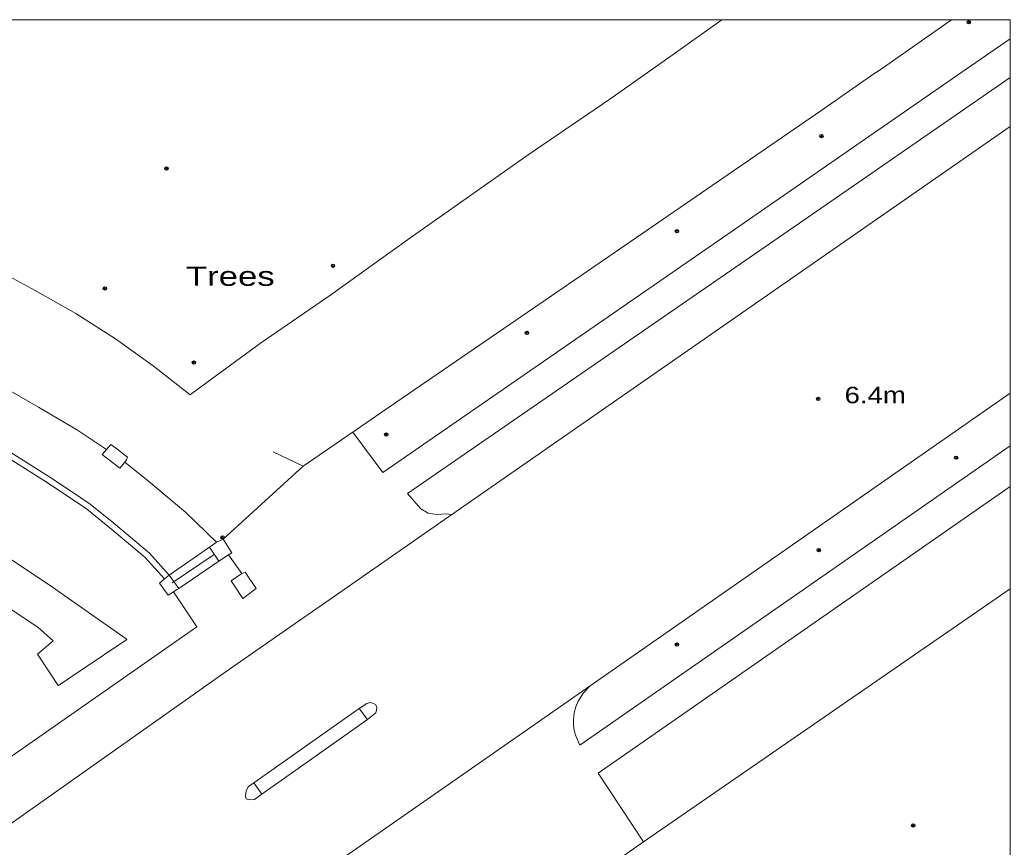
# Model space of a CAD drawing. Extents: x 528790 to 529292, y 179350 to 179856.
# Drawn here: x 529200.1 to 529290.2, y 179780.8 to 179856 of the extents above; entities that cross this region are included whole.
import ezdxf

# ---------------------------------------------------------------- set-up
doc = ezdxf.new("R2010")
doc.units = 0
doc.header["$LTSCALE"] = 0.6
doc.header["$PDMODE"] = 32
doc.header["$PDSIZE"] = 0.3
for name, color, linetype, lineweight in [('1', 7, 'Continuous', 13), ('2', 7, 'Continuous', 13), ('7', 7, 'Continuous', 13)]:
    doc.layers.add(name, color=color, linetype=linetype, lineweight=lineweight)
for name, color, linetype in [('3', 7, 'Continuous'), ('4', 7, 'Continuous'), ('5', 7, 'Continuous')]:
    doc.layers.add(name, color=color, linetype=linetype)

msp = doc.modelspace()

# ---------------------------------------------------------------- linework, layer by layer
at = {"layer": '1'}
for points in [[(529198.5, 179833.05), (529201.5, 179831.4), (529205.2, 179829.3), (529208.8, 179827), (529212.25, 179824.55), (529215.6, 179821.9), (529215.75, 179822.05), (529222, 179826.6), (529228.4, 179831), (529235.6, 179836.15), (529246.35, 179843.75), (529253.8, 179848.8), (529259.25, 179852.65), (529263.987, 179856.024), (529112.683, 179856.024)], [(529263.987, 179856.024), (529259.25, 179852.65), (529253.8, 179848.8), (529246.35, 179843.75), (529235.6, 179836.15), (529228.4, 179831), (529222, 179826.6), (529215.75, 179822.05), (529215.6, 179821.9), (529212.25, 179824.55), (529208.8, 179827), (529205.2, 179829.3), (529201.5, 179831.4), (529198.5, 179833.05)], [(529198.65, 179822.6), (529201.8, 179820.8), (529205.35, 179818.7), (529208, 179816.95), (529208.4, 179817.4), (529208.8, 179817.1), (529209.9, 179816.25), (529209.8, 179816), (529209.65, 179815.8), (529211.8, 179814.05), (529215.2, 179811.2), (529218, 179808.5), (529218.6, 179808.8), (529225.892, 179815.426), (529230.35, 179818.5), (529230.391, 179818.529), (529233.25, 179820.5), (529252.25, 179833.5), (529273, 179847.75), (529277.8, 179851.1), (529278.3, 179851.4), (529284.881, 179856.024), (529263.987, 179856.024)], [(529193.75, 179779.8), (529195, 179780.25), (529196.2, 179780.75), (529215.881, 179794.64), (529218.8, 179796.7), (529225.868, 179801.613), (529227.601, 179802.818), (529239.4, 179811.019), (529238.871, 179811.099), (529238.043, 179811.018), (529237.268, 179811.152), (529236.6, 179811.553), (529235.371, 179812.942), (529272.218, 179838.358), (529290.22, 179850.775), (529290.22, 179854.287)], [(529290.22, 179854.287), (529285.342, 179850.916), (529263.256, 179835.656), (529233.132, 179814.843), (529230.391, 179818.529), (529230.35, 179818.5), (529225.892, 179815.426), (529218.6, 179808.8), (529219.4, 179807.55), (529219.1, 179807.35), (529218.2, 179806.8), (529214.561, 179804.31), (529214.399, 179804.201), (529214.1, 179804), (529216.2, 179800.8), (529193.95, 179785.3)], [(529198.467, 179817.178), (529202.731, 179814.497), (529205.276, 179812.817), (529206.507, 179811.975), (529208.647, 179810.233), (529211.903, 179807.505), (529213.704, 179805.508), (529217.35, 179808.05), (529218, 179808.5), (529215.2, 179811.2), (529211.8, 179814.05), (529209.65, 179815.8), (529209.2, 179815.25), (529207.6, 179816.5), (529208, 179816.95), (529205.35, 179818.7), (529201.8, 179820.8), (529198.65, 179822.6)], [(529290.22, 179817.266), (529251.05, 179790.05), (529250.7, 179790.9), (529250.55, 179791.4), (529250.5, 179791.9), (529250.5, 179792.4), (529250.55, 179793), (529250.7, 179793.55), (529250.9, 179794.05), (529251.4, 179794.8), (529252, 179795.45), (529230.4, 179780.4)], [(529253.6, 179779), (529256.852, 179781.245), (529252.72, 179787.516), (529290.22, 179813.583), (529290.22, 179817.266)], [(529193.95, 179785.3), (529216.2, 179800.8), (529214.1, 179804), (529213.6, 179803.7), (529212.8, 179804.8), (529213.266, 179805.173), (529211.52, 179807.108), (529208.297, 179809.809), (529206.178, 179811.534), (529204.969, 179812.36), (529202.433, 179814.035), (529198.187, 179816.704)], [(529198.187, 179816.704), (529202.433, 179814.035), (529204.969, 179812.36), (529206.178, 179811.534), (529208.297, 179809.809), (529211.52, 179807.108), (529213.266, 179805.173), (529213.554, 179805.394), (529213.694, 179805.501), (529213.704, 179805.508), (529211.903, 179807.505), (529208.647, 179810.233), (529206.507, 179811.975), (529205.276, 179812.817), (529202.731, 179814.497), (529198.467, 179817.178)], [(529199.16, 179807.038), (529202.771, 179804.622), (529209.769, 179799.718), (529209.837, 179799.67), (529205.674, 179796.869), (529203.893, 179795.67), (529203.606, 179795.477), (529201.699, 179798.343), (529203.13, 179799.547), (529201.74, 179800.789), (529196.758, 179804.067)], [(529196.758, 179804.067), (529201.74, 179800.789), (529203.13, 179799.547), (529201.699, 179798.343), (529203.606, 179795.477), (529203.893, 179795.67), (529205.674, 179796.869), (529209.837, 179799.67), (529209.769, 179799.718), (529202.771, 179804.622), (529199.16, 179807.038)]]:
    msp.add_lwpolyline(points, dxfattribs=at)
for points in [[(529290.22, 179854.287), (529290.22, 179856.024), (529284.881, 179856.024), (529278.3, 179851.4), (529277.8, 179851.1), (529273, 179847.75), (529252.25, 179833.5), (529233.25, 179820.5), (529230.391, 179818.529), (529233.132, 179814.843), (529263.256, 179835.656), (529285.342, 179850.916)], [(529290.22, 179850.775), (529272.218, 179838.358), (529235.371, 179812.942), (529236.6, 179811.553), (529237.268, 179811.152), (529238.043, 179811.018), (529238.871, 179811.099), (529239.4, 179811.019), (529239.43, 179811.04), (529239.8, 179811.3), (529290.22, 179846.321)], [(529290.22, 179846.321), (529239.8, 179811.3), (529239.43, 179811.04), (529239.4, 179811.019), (529227.601, 179802.818), (529225.868, 179801.613), (529218.8, 179796.7), (529215.881, 179794.64), (529196.2, 179780.75), (529195, 179780.25), (529206.62, 179763.69), (529206.95, 179764.05), (529207.9, 179764.9), (529208.95, 179765.8), (529227.282, 179778.278), (529230.4, 179780.4), (529252, 179795.45), (529290.22, 179822.055)], [(529290.22, 179822.055), (529252, 179795.45), (529251.4, 179794.8), (529250.9, 179794.05), (529250.7, 179793.55), (529250.55, 179793), (529250.5, 179792.4), (529250.5, 179791.9), (529250.55, 179791.4), (529250.7, 179790.9), (529251.05, 179790.05), (529290.22, 179817.266)], [(529209.65, 179815.8), (529209.8, 179816), (529209.9, 179816.25), (529208.8, 179817.1), (529208.4, 179817.4), (529208, 179816.95), (529207.6, 179816.5), (529209.2, 179815.25)], [(529290.22, 179804.278), (529290.22, 179813.583), (529252.72, 179787.516), (529256.852, 179781.245)], [(529217.35, 179808.05), (529218.2, 179806.8), (529219.1, 179807.35), (529219.4, 179807.55), (529218.6, 179808.8), (529218, 179808.5)], [(529218.2, 179806.8), (529217.35, 179808.05), (529213.704, 179805.508), (529214.561, 179804.31)], [(529220.3, 179805.65), (529219.35, 179805), (529220.4, 179803.4), (529221.6, 179804.3), (529220.6, 179805.8)], [(529219.35, 179805), (529220.3, 179805.65), (529220.6, 179805.8), (529221.6, 179804.3), (529220.4, 179803.4)], [(529214.1, 179804), (529214.399, 179804.201), (529214.561, 179804.31), (529213.704, 179805.508), (529213.694, 179805.501), (529213.554, 179805.394), (529213.266, 179805.173), (529212.8, 179804.8), (529213.6, 179803.7)], [(529290.22, 179741.025), (529290.22, 179804.278), (529256.852, 179781.245), (529253.6, 179779), (529255.4, 179776.05), (529259.35, 179770.4), (529259.95, 179769.5), (529260.9, 179767.8), (529261.4, 179766.7), (529269.1, 179751.6), (529270.75, 179748.3), (529271.8, 179745.9), (529272.75, 179744), (529274.8, 179738.75), (529275, 179738.3), (529275.7, 179737.7), (529276.2, 179737.4), (529276.75, 179737.3), (529277.95, 179737.1), (529278.9, 179737.15), (529279.8, 179737.25), (529281, 179737.6), (529285.6, 179739.3)], [(529220.713, 179785.172), (529220.63, 179785.444), (529220.714, 179785.863), (529220.887, 179786.269), (529221.409, 179786.636), (529230.996, 179793.382), (529231.668, 179793.855), (529231.999, 179793.935), (529232.297, 179793.852), (529232.506, 179793.705), (529232.59, 179793.475), (529232.569, 179793.266), (529232.485, 179792.994), (529231.754, 179792.385), (529222.137, 179785.609), (529221.99, 179785.506), (529221.466, 179785.109), (529220.985, 179785.088)], [(529232.485, 179792.994), (529232.569, 179793.266), (529232.59, 179793.475), (529232.506, 179793.705), (529232.297, 179793.852), (529231.999, 179793.935), (529231.668, 179793.855), (529230.996, 179793.382), (529231.754, 179792.385)], [(529231.754, 179792.385), (529230.996, 179793.382), (529221.409, 179786.636), (529222.137, 179785.609)], [(529222.137, 179785.609), (529221.409, 179786.636), (529220.887, 179786.269), (529220.714, 179785.863), (529220.63, 179785.444), (529220.713, 179785.172), (529220.985, 179785.088), (529221.466, 179785.109), (529221.99, 179785.506)]]:
    msp.add_lwpolyline(points, close=True, dxfattribs=at)
at = {"layer": '2'}
for p, q in [((529277.8, 179851.1), (529273, 179847.75)), ((529252, 179795.45), (529290.22, 179822.055)), ((529225.892, 179815.426), (529223.147, 179816.729)), ((529225.892, 179815.426), (529218.6, 179808.8)), ((529227.601, 179802.818), (529239.4, 179811.019)), ((529217.35, 179808.05), (529218, 179808.5)), ((529218, 179808.5), (529218.6, 179808.8)), ((529217.35, 179808.05), (529213.704, 179805.508)), ((529213.97, 179804.81), (529217.79, 179807.4)), ((529218.2, 179806.8), (529217.35, 179808.05)), ((529219.1, 179807.35), (529218.2, 179806.8)), ((529219.1, 179807.35), (529220.3, 179805.65)), ((529218.2, 179806.8), (529214.561, 179804.31)), ((529213.704, 179805.508), (529214.561, 179804.31)), ((529256.852, 179781.245), (529290.22, 179804.278)), ((529227.601, 179802.818), (529225.868, 179801.613)), ((529221.409, 179786.636), (529230.996, 179793.382)), ((529230.996, 179793.382), (529231.754, 179792.385)), ((529231.754, 179792.385), (529222.137, 179785.609)), ((529221.409, 179786.636), (529222.137, 179785.609)), ((529253.6, 179779), (529256.852, 179781.245))]:
    msp.add_line(p, q, dxfattribs=at)
for points in [[(529198.5, 179833.05), (529201.5, 179831.4), (529205.2, 179829.3), (529208.8, 179827), (529212.25, 179824.55), (529215.6, 179821.9), (529215.75, 179822.05), (529222, 179826.6), (529228.4, 179831), (529235.6, 179836.15), (529246.35, 179843.75), (529253.8, 179848.8), (529259.25, 179852.65), (529263.987, 179856.024)], [(529284.881, 179856.024), (529278.3, 179851.4), (529277.8, 179851.1)], [(529230.391, 179818.529), (529233.132, 179814.843), (529263.256, 179835.656), (529285.342, 179850.916), (529290.22, 179854.287)], [(529290.22, 179850.775), (529272.218, 179838.358), (529235.371, 179812.942), (529236.6, 179811.553), (529237.268, 179811.152), (529238.043, 179811.018), (529238.871, 179811.099), (529239.4, 179811.019)], [(529230.391, 179818.529), (529233.25, 179820.5), (529252.25, 179833.5), (529273, 179847.75)], [(529239.4, 179811.019), (529239.43, 179811.04), (529239.8, 179811.3), (529290.22, 179846.321)], [(529198.65, 179822.6), (529201.8, 179820.8), (529205.35, 179818.7), (529208, 179816.95)], [(529225.892, 179815.426), (529230.35, 179818.5), (529230.391, 179818.529)], [(529208, 179816.95), (529208.4, 179817.4), (529208.8, 179817.1), (529209.9, 179816.25), (529209.8, 179816), (529209.65, 179815.8)], [(529252, 179795.45), (529251.4, 179794.8), (529250.9, 179794.05), (529250.7, 179793.55), (529250.55, 179793), (529250.5, 179792.4), (529250.5, 179791.9), (529250.55, 179791.4), (529250.7, 179790.9), (529251.05, 179790.05), (529290.22, 179817.266)], [(529213.266, 179805.173), (529211.52, 179807.108), (529208.297, 179809.809), (529206.178, 179811.534), (529204.969, 179812.36), (529202.433, 179814.035), (529198.187, 179816.704)], [(529213.704, 179805.508), (529211.903, 179807.505), (529208.647, 179810.233), (529206.507, 179811.975), (529205.276, 179812.817), (529202.731, 179814.497), (529198.467, 179817.178)], [(529209.65, 179815.8), (529209.2, 179815.25), (529207.6, 179816.5), (529208, 179816.95)], [(529218, 179808.5), (529215.2, 179811.2), (529211.8, 179814.05), (529209.65, 179815.8)], [(529256.852, 179781.245), (529252.72, 179787.516), (529290.22, 179813.583)], [(529218.6, 179808.8), (529219.4, 179807.55), (529219.1, 179807.35)], [(529196.758, 179804.067), (529201.74, 179800.789), (529203.13, 179799.547), (529201.699, 179798.343), (529203.606, 179795.477), (529203.893, 179795.67), (529205.674, 179796.869), (529209.837, 179799.67), (529209.769, 179799.718), (529202.771, 179804.622), (529199.16, 179807.038)], [(529214.1, 179804), (529213.6, 179803.7), (529212.8, 179804.8), (529213.266, 179805.173)], [(529213.266, 179805.173), (529213.554, 179805.394), (529213.694, 179805.501), (529213.704, 179805.508)], [(529214.1, 179804), (529216.2, 179800.8), (529193.95, 179785.3)], [(529214.561, 179804.31), (529214.399, 179804.201), (529214.1, 179804)], [(529225.868, 179801.613), (529218.8, 179796.7), (529215.881, 179794.64)], [(529227.282, 179778.278), (529230.4, 179780.4), (529252, 179795.45)], [(529215.881, 179794.64), (529196.2, 179780.75), (529195, 179780.25)], [(529230.996, 179793.382), (529231.668, 179793.855), (529231.999, 179793.935), (529232.297, 179793.852), (529232.506, 179793.705), (529232.59, 179793.475), (529232.569, 179793.266), (529232.485, 179792.994), (529231.754, 179792.385)], [(529222.137, 179785.609), (529221.99, 179785.506), (529221.466, 179785.109), (529220.985, 179785.088), (529220.713, 179785.172), (529220.63, 179785.444), (529220.714, 179785.863), (529220.887, 179786.269), (529221.409, 179786.636)]]:
    msp.add_lwpolyline(points, dxfattribs=at)
msp.add_lwpolyline([(529220.3, 179805.65), (529220.6, 179805.8), (529221.6, 179804.3), (529220.4, 179803.4), (529219.35, 179805)], close=True, dxfattribs=at)
at = {"layer": '3'}
for p in [(529286.45, 179855.8), (529273.05, 179845.45), (529213.45, 179842.5), (529259.9, 179836.8), (529228.6, 179833.65), (529207.85, 179831.6), (529246.25, 179827.55), (529215.95, 179824.85), (529272.75, 179821.55), (529233.45, 179818.3), (529285.3, 179816.2), (529272.8, 179807.8), (529259.9, 179799.2), (529281.4, 179782.75)]:
    msp.add_point(p, dxfattribs=at)
at = {"layer": '4'}
msp.add_point((529218.55, 179808.95), dxfattribs=at)
at = {"layer": '7'}
msp.add_lwpolyline([(528790.22, 179356.024), (529290.22, 179356.024), (529290.22, 179856.024), (528790.22, 179856.024)], close=True, dxfattribs=at)

# ---------------------------------------------------------------- texts
at = {"layer": '5'}
for s, height, width, p in [('Trees', 1.75, 1.35, (529215.22, 179831.83)), ('6.4m', 1.5, 1.25, (529275.15, 179821.15))]:
    msp.add_text(s, height=height, dxfattribs=dict(at, width=width)).set_placement(p)

doc.saveas('drawing.dxf')
